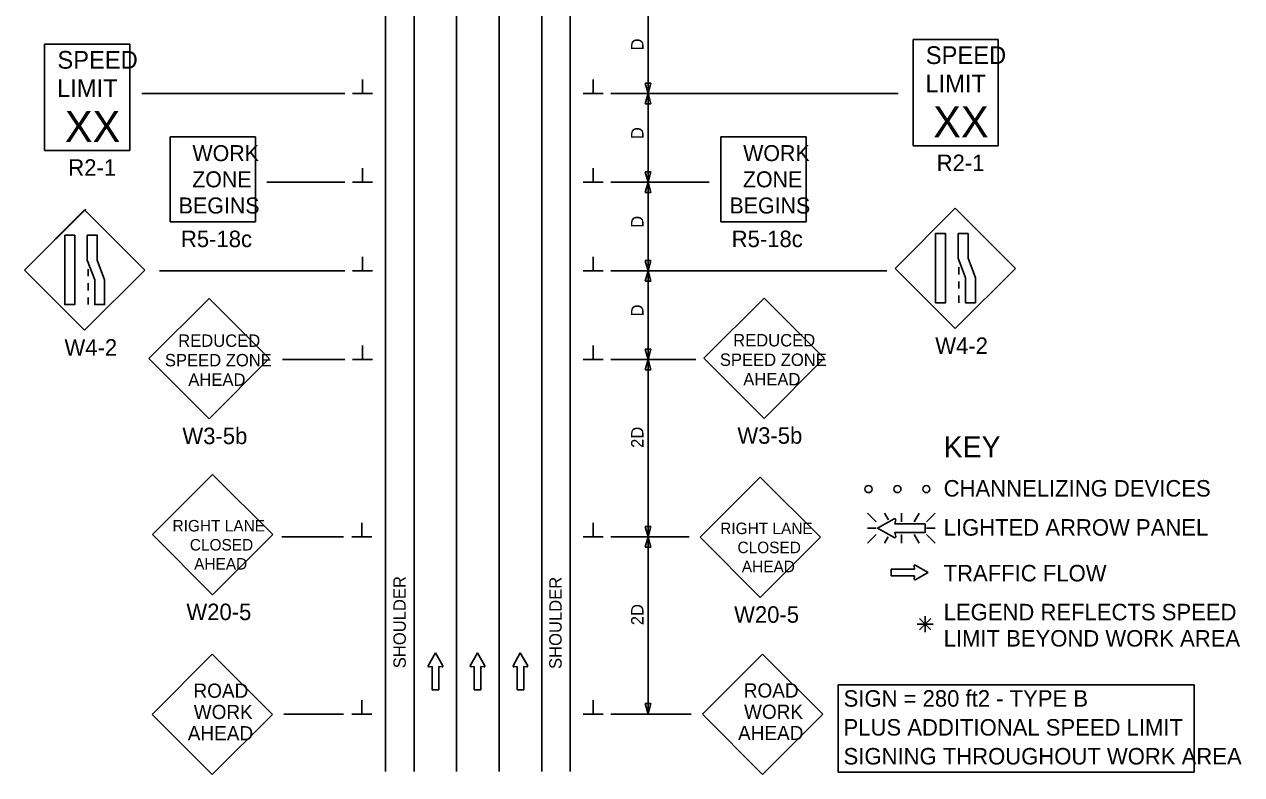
# Model space of a CAD drawing. Extents: x 16730 to 18475, y 5690 to 6927.
# Drawn here: x 16747 to 17434, y 6106 to 6529 of the extents above; entities that cross this region are included whole.
import ezdxf

# ---------------------------------------------------------------- set-up
doc = ezdxf.new("R2010")
doc.units = 0
for name, color, linetype in [('ALI_LEGAL_EX', 7, 'Continuous'), ('MT_SCRATCH_LEVEL_E', 7, 'Continuous'), ('PAVT_EDGE_EX', 7, 'Continuous'), ('TRAFFIC_SIGNS_PR', 7, 'Continuous'), ('TYPICAL_TEXT_DIMEN_EX', 7, 'Continuous'), ('TYPICAL_TEXT_DIMEN_PR', 7, 'Continuous')]:
    doc.layers.add(name, color=color, linetype=linetype)

msp = doc.modelspace()

# ---------------------------------------------------------------- linework, layer by layer
at = {"layer": 'ALI_LEGAL_EX'}
for p, q in [((16991.15, 6924.81), (16991.15, 6107.83)), ((17015.15, 6924.81), (17015.15, 6107.83))]:
    msp.add_line(p, q, dxfattribs=at)
for points in [[(16991.15, 6524.81), (16991.15, 6499.81)], [(17015.15, 6524.81), (17015.15, 6499.81)], [(16991.15, 6474.81), (16991.15, 6449.81)], [(17015.15, 6474.81), (17015.15, 6449.81)], [(16991.15, 6424.81), (16991.15, 6399.81)], [(17015.15, 6424.81), (17015.15, 6399.81)], [(16991.15, 6324.81), (16991.15, 6299.81)], [(17015.15, 6324.81), (17015.15, 6299.81)], [(16991.15, 6224.81), (16991.15, 6199.81)], [(17015.15, 6224.81), (17015.15, 6199.81)], [(16991.15, 6124.81), (16991.15, 6107.83)], [(17015.15, 6124.81), (17015.15, 6107.83)]]:
    msp.add_lwpolyline(points, dxfattribs=at)
at = {"layer": 'MT_SCRATCH_LEVEL_E'}
for p, q in [((17249.52, 6222.01), (17236.26, 6222.01)), ((17236.26, 6222.01), (17236.26, 6218.27)), ((17249.21, 6223.79), (17249.52, 6222.01)), ((17257.13, 6220.16), (17249.89, 6224.27)), ((17236.26, 6218.27), (17249.52, 6218.27)), ((17249.52, 6218.27), (17249.21, 6216.49)), ((17249.89, 6216.01), (17257.13, 6220.16)), ((16979.3, 6174.71), (16975.19, 6167.47)), ((16983.44, 6167.47), (16979.3, 6174.71)), ((17003, 6174.71), (16998.89, 6167.47)), ((17007.15, 6167.47), (17003, 6174.71)), ((17027.11, 6174.71), (17023, 6167.47)), ((17031.26, 6167.47), (17027.11, 6174.71)), ((16975.67, 6166.78), (16977.45, 6167.1)), ((16977.45, 6167.1), (16977.45, 6153.84)), ((16981.19, 6153.84), (16981.19, 6167.1)), ((16981.19, 6167.1), (16982.97, 6166.78)), ((16999.37, 6166.78), (17001.15, 6167.1)), ((17001.15, 6167.1), (17001.15, 6153.84)), ((17004.89, 6153.84), (17004.89, 6167.1)), ((17004.89, 6167.1), (17006.67, 6166.78)), ((17023.48, 6166.78), (17025.26, 6167.1)), ((17025.26, 6167.1), (17025.26, 6153.84)), ((17029, 6153.84), (17029, 6167.1)), ((17029, 6167.1), (17030.78, 6166.78)), ((16977.45, 6153.84), (16981.19, 6153.84)), ((17001.15, 6153.84), (17004.89, 6153.84)), ((17025.26, 6153.84), (17029, 6153.84))]:
    msp.add_line(p, q, dxfattribs=at)
for centre, start, end in [((17249.66, 6223.86), 60.42484, 189.96381), ((17249.66, 6216.42), 170.03619, 299.77312), ((16975.59, 6167.24), 150.42484, 279.96381), ((16983.04, 6167.25), 260.03619, 29.77312), ((16999.3, 6167.24), 150.42484, 279.96381), ((17006.74, 6167.25), 260.03619, 29.77312), ((17023.41, 6167.24), 150.42484, 279.96381), ((17030.85, 6167.25), 260.03619, 29.77312)]:
    msp.add_arc(centre, 0.463, start, end, dxfattribs=at)
at = {"layer": 'PAVT_EDGE_EX'}
for p, q in [((16951.15, 6927.15), (16951.15, 6107.83)), ((16967.15, 6927.15), (16967.15, 6107.83)), ((17039.15, 6927.15), (17039.15, 6107.83)), ((17055.15, 6927.15), (17055.15, 6107.83))]:
    msp.add_line(p, q, dxfattribs=at)
at = {"layer": 'TRAFFIC_SIGNS_PR'}
for p, q in [((16758.8, 6518.11), (16806.8, 6518.11)), ((16758.8, 6458.11), (16758.8, 6518.11)), ((16806.8, 6458.11), (16806.8, 6518.11)), ((17248.6, 6520.74), (17296.6, 6520.74)), ((17248.6, 6460.74), (17248.6, 6520.74)), ((17296.6, 6460.74), (17296.6, 6520.74)), ((16829.68, 6417.85), (16829.68, 6465.85)), ((16829.68, 6465.85), (16877.68, 6465.85)), ((16877.68, 6417.85), (16877.68, 6465.85)), ((17140.3, 6417.85), (17140.3, 6465.85)), ((17140.3, 6465.85), (17188.3, 6465.85)), ((17188.3, 6417.85), (17188.3, 6465.85)), ((16758.8, 6458.11), (16806.8, 6458.11)), ((17248.6, 6460.74), (17296.6, 6460.74)), ((16781.3, 6424.52), (16747.36, 6390.58)), ((16782, 6425.03), (16748.05, 6391.09)), ((16815.24, 6390.58), (16781.3, 6424.52)), ((17272.45, 6425.51), (17238.51, 6391.57)), ((17306.39, 6391.57), (17272.45, 6425.51)), ((16829.68, 6417.85), (16877.68, 6417.85)), ((17140.3, 6417.85), (17188.3, 6417.85)), ((16747.36, 6390.58), (16781.3, 6356.64)), ((16781.3, 6356.64), (16815.24, 6390.58)), ((16783.35, 6391.19), (16783.35, 6387.19)), ((17238.51, 6391.57), (17272.45, 6357.63)), ((17272.45, 6357.63), (17306.39, 6391.57)), ((17274.5, 6392.19), (17274.5, 6388.19)), ((16783.35, 6383.19), (16783.35, 6379.19)), ((17274.5, 6384.19), (17274.5, 6380.19)), ((16783.35, 6375.19), (16783.35, 6371.19)), ((16851.56, 6374.63), (16817.62, 6340.69)), ((16885.5, 6340.69), (16851.56, 6374.63)), ((17164.59, 6374.86), (17130.65, 6340.92)), ((17198.53, 6340.92), (17164.59, 6374.86)), ((17274.5, 6376.19), (17274.5, 6372.19)), ((16817.62, 6340.69), (16851.56, 6306.75)), ((16851.56, 6306.75), (16885.5, 6340.69)), ((17130.65, 6340.92), (17164.59, 6306.98)), ((17164.59, 6306.98), (17198.53, 6340.92)), ((16853.55, 6275.39), (16819.61, 6241.44)), ((16887.5, 6241.44), (16853.55, 6275.39)), ((17162.47, 6273.91), (17128.53, 6239.97)), ((17196.41, 6239.97), (17162.47, 6273.91)), ((17222.94, 6253.54), (17227.87, 6248.61)), ((17234.7, 6249.72), (17232.5, 6253.55)), ((17242.02, 6248.61), (17242.02, 6253.55)), ((17249.26, 6248.61), (17252.11, 6253.55)), ((17256.17, 6248.61), (17261.11, 6253.55)), ((16819.61, 6241.44), (16853.55, 6207.5)), ((16853.55, 6207.5), (16887.5, 6241.44)), ((17227.87, 6245.06), (17222.94, 6245.06)), ((17222.94, 6236.57), (17227.87, 6241.5)), ((17242.02, 6241.5), (17242.02, 6236.57)), ((17252.15, 6236.57), (17249.3, 6241.5)), ((17256.17, 6245.06), (17261.11, 6245.06)), ((17256.17, 6241.5), (17261.11, 6236.56)), ((17128.53, 6239.97), (17162.47, 6206.03)), ((17162.47, 6206.03), (17196.41, 6239.97)), ((17232.45, 6236.57), (17234.56, 6240.23)), ((16853.35, 6173.94), (16819.4, 6140)), ((16887.29, 6140), (16853.35, 6173.94)), ((17163.72, 6174.07), (17129.78, 6140.13)), ((17197.66, 6140.13), (17163.72, 6174.07)), ((16819.4, 6140), (16853.35, 6106.06)), ((16853.35, 6106.06), (16887.29, 6140)), ((17129.78, 6140.13), (17163.72, 6106.18)), ((17163.72, 6106.18), (17197.66, 6140.13))]:
    msp.add_line(p, q, dxfattribs=at)
for points in [[(16770.18, 6410.25), (16770.18, 6371.19), (16775.8, 6371.19), (16775.8, 6410.25)], [(16782.85, 6410.25), (16782.85, 6396.27), (16787.03, 6385.17), (16787.03, 6371.19), (16792.65, 6371.19), (16792.65, 6385.17), (16788.47, 6396.27), (16788.47, 6410.25)], [(17261.33, 6411.24), (17261.33, 6372.19), (17266.95, 6372.19), (17266.95, 6411.24)], [(17274, 6411.24), (17274, 6397.27), (17278.18, 6386.16), (17278.18, 6372.19), (17283.8, 6372.19), (17283.8, 6386.16), (17279.62, 6397.27), (17279.62, 6411.24)]]:
    msp.add_lwpolyline(points, close=True, dxfattribs=at)
for points in [[(17237.95, 6250.33), (17228.66, 6245.06), (17237.95, 6239.73)], [(17238.83, 6240.36), (17238.42, 6242.63), (17255.44, 6242.63), (17255.44, 6247.43), (17238.42, 6247.43), (17238.83, 6249.71)]]:
    msp.add_lwpolyline(points, dxfattribs=at)
for centre in [(17223.5, 6267.09), (17239.8, 6267.09), (17256.1, 6267.09)]:
    msp.add_circle(centre, 2, dxfattribs=at)
for centre, radius, start, end in [((17238.24, 6249.81), 0.598, 350.73078, 118.89165), ((17238.24, 6240.26), 0.597, 241.48329, 9.95933)]:
    msp.add_arc(centre, radius, start, end, dxfattribs=at)
at = {"layer": 'TYPICAL_TEXT_DIMEN_EX'}
msp.add_lwpolyline([(17206.43, 6156.8), (17407.1, 6156.8), (17407.1, 6107.48), (17206.43, 6107.48)], close=True, dxfattribs=at)
at = {"layer": 'TYPICAL_TEXT_DIMEN_PR'}
for p, q in [((17099.15, 6540.24), (17099.15, 6490.24)), ((16938.03, 6490.24), (16938.03, 6498.02)), ((17068.28, 6490.24), (17068.28, 6498.02)), ((17099.15, 6490.24), (17097.58, 6496.1)), ((17097.58, 6496.1), (17099.15, 6496.1)), ((17099.15, 6496.1), (17100.72, 6496.1)), ((17100.72, 6496.1), (17099.15, 6490.24)), ((16813.56, 6490.24), (16928.15, 6490.24)), ((16932.4, 6490.24), (16943.65, 6490.24)), ((17073.9, 6490.24), (17062.65, 6490.24)), ((17240.31, 6490.24), (17078.15, 6490.24)), ((17097.58, 6484.38), (17099.15, 6490.24)), ((17099.15, 6490.24), (17099.15, 6440.24)), ((17099.15, 6490.24), (17100.72, 6484.38)), ((17099.15, 6484.38), (17097.58, 6484.38)), ((17100.72, 6484.38), (17099.15, 6484.38)), ((16938.03, 6440.24), (16938.03, 6448.02)), ((17068.28, 6440.24), (17068.28, 6448.02)), ((17099.15, 6440.24), (17097.58, 6446.1)), ((17097.58, 6446.1), (17099.15, 6446.1)), ((17099.15, 6446.1), (17100.72, 6446.1)), ((17100.72, 6446.1), (17099.15, 6440.24)), ((16884.19, 6440.24), (16928.15, 6440.24)), ((16932.4, 6440.24), (16943.65, 6440.24)), ((17073.9, 6440.24), (17062.65, 6440.24)), ((17133.63, 6440.24), (17078.15, 6440.24)), ((17097.58, 6434.38), (17099.15, 6440.24)), ((17099.15, 6434.38), (17097.58, 6434.38)), ((17099.15, 6440.24), (17099.15, 6390.24)), ((17099.15, 6440.24), (17100.72, 6434.38)), ((17100.72, 6434.38), (17099.15, 6434.38)), ((16938.03, 6390.24), (16938.03, 6398.02)), ((17068.28, 6390.24), (17068.28, 6398.02)), ((17099.15, 6390.24), (17097.58, 6396.1)), ((17097.58, 6396.1), (17099.15, 6396.1)), ((17099.15, 6396.1), (17100.72, 6396.1)), ((17100.72, 6396.1), (17099.15, 6390.24)), ((16823.56, 6390.24), (16928.15, 6390.24)), ((16932.4, 6390.24), (16943.65, 6390.24)), ((17073.9, 6390.24), (17062.65, 6390.24)), ((17233.8, 6390.24), (17078.15, 6390.24)), ((17097.58, 6384.38), (17099.15, 6390.24)), ((17099.15, 6390.24), (17099.15, 6340.24)), ((17099.15, 6390.24), (17100.72, 6384.38)), ((17099.15, 6384.38), (17097.58, 6384.38)), ((17100.72, 6384.38), (17099.15, 6384.38)), ((16938.03, 6340.24), (16938.03, 6348.02)), ((17068.28, 6340.24), (17068.28, 6348.02)), ((17099.15, 6340.24), (17097.58, 6346.1)), ((17097.58, 6346.1), (17099.15, 6346.1)), ((17099.15, 6346.1), (17100.72, 6346.1)), ((17100.72, 6346.1), (17099.15, 6340.24)), ((16892.99, 6340.24), (16928.15, 6340.24)), ((16932.4, 6340.24), (16943.65, 6340.24)), ((17073.9, 6340.24), (17062.65, 6340.24)), ((17126.13, 6340.24), (17078.15, 6340.24)), ((17097.58, 6334.38), (17099.15, 6340.24)), ((17099.15, 6340.24), (17099.15, 6240.24)), ((17099.15, 6340.24), (17100.72, 6334.38)), ((17099.15, 6334.38), (17097.58, 6334.38)), ((17100.72, 6334.38), (17099.15, 6334.38)), ((16937.74, 6240.24), (16937.74, 6248.02)), ((17068.28, 6240.24), (17068.28, 6248.02)), ((17099.15, 6240.24), (17097.58, 6246.1)), ((17097.58, 6246.1), (17099.15, 6246.1)), ((17099.15, 6246.1), (17100.72, 6246.1)), ((17100.72, 6246.1), (17099.15, 6240.24)), ((16927.29, 6240.24), (16892.61, 6240.24)), ((16943.36, 6240.24), (16932.11, 6240.24)), ((17073.9, 6240.24), (17062.65, 6240.24)), ((17122.42, 6240.24), (17078.15, 6240.24)), ((17097.58, 6234.38), (17099.15, 6240.24)), ((17099.15, 6240.24), (17099.15, 6140.24)), ((17099.15, 6240.24), (17100.72, 6234.38)), ((17099.15, 6234.38), (17097.58, 6234.38)), ((17100.72, 6234.38), (17099.15, 6234.38)), ((17252.28, 6194.1), (17258.65, 6187.73)), ((17258.65, 6194.1), (17252.28, 6187.73)), ((17255.46, 6190.91), (17255.46, 6195.37)), ((17255.46, 6190.91), (17250.93, 6190.91)), ((17255.46, 6190.91), (17258.65, 6190.91)), ((17255.46, 6190.91), (17259.94, 6190.91)), ((17255.46, 6190.91), (17255.46, 6186.41)), ((16937.74, 6140.24), (16937.74, 6148.02)), ((17068.28, 6140.24), (17068.28, 6148.02)), ((17099.15, 6140.24), (17097.58, 6146.1)), ((17097.58, 6146.1), (17099.15, 6146.1)), ((17099.15, 6146.1), (17100.72, 6146.1)), ((17100.72, 6146.1), (17099.15, 6140.24)), ((16927.29, 6140.24), (16893.73, 6140.24)), ((16943.36, 6140.24), (16932.11, 6140.24)), ((17073.9, 6140.24), (17062.65, 6140.24)), ((17123.54, 6140.24), (17078.15, 6140.24))]:
    msp.add_line(p, q, dxfattribs=at)

# ---------------------------------------------------------------- texts
at = {"layer": 'TRAFFIC_SIGNS_PR'}
for s, height, p in [('SPEED', 10, (17255.81, 6506.82)), ('SPEED', 10, (16766.01, 6504.19)), ('LIMIT', 10, (16765.81, 6488.19)), ('LIMIT', 10, (17255.6, 6490.82)), ('XX', 17.538, (17259.99, 6465.44)), ('XX', 17.538, (16770.19, 6462.81)), ('WORK', 9.021, (16842.18, 6452.06)), ('WORK', 9.021, (17152.8, 6452.06)), ('R2-1', 9.3, (17261.94, 6446.44)), ('R2-1', 9.3, (16772.15, 6443.81)), ('ZONE', 9.021, (16842.03, 6437.29)), ('ZONE', 9.021, (17152.65, 6437.29)), ('BEGINS', 9.021, (16834.44, 6422.53)), ('BEGINS', 9.021, (17145.06, 6422.53)), ('R5-18c', 9.3, (16835.69, 6403.55)), ('R5-18c', 9.3, (17146.32, 6403.55)), ('W4-2', 9.3, (16770, 6342.34)), ('REDUCED', 7, (16834.13, 6347.32)), ('REDUCED', 7, (17147.16, 6347.56)), ('W4-2', 9.3, (17261.15, 6343.33)), ('SPEED ZONE', 7, (16826.63, 6336.32)), ('SPEED ZONE', 7, (17139.65, 6336.56)), ('AHEAD', 7, (16839.83, 6325.32)), ('AHEAD', 7, (17152.85, 6325.56)), ('W3-5b', 9.3, (16836.5, 6292.45)), ('W3-5b', 9.3, (17149.53, 6292.68)), ('RIGHT LANE', 6.5, (16830.96, 6243.19)), ('RIGHT LANE', 6.5, (17139.87, 6241.71)), ('CLOSED', 6.5, (16840.7, 6232.44)), ('CLOSED', 6.5, (17149.61, 6230.96)), ('AHEAD', 6.5, (16843.13, 6221.69)), ('AHEAD', 6.5, (17152.05, 6220.21)), ('W20-5', 9.3, (16838.77, 6193.21)), ('W20-5', 9.3, (17147.69, 6191.73)), ('ROAD', 8, (16842.77, 6149.42)), ('ROAD', 8, (17153.15, 6149.54)), ('WORK', 8, (16842.91, 6137.42)), ('WORK', 8, (17153.28, 6137.54)), ('AHEAD', 8, (16839.55, 6125.42)), ('AHEAD', 8, (17149.92, 6125.54))]:
    msp.add_text(s, height=height, dxfattribs=at).set_placement(p)
at = {"layer": 'TYPICAL_TEXT_DIMEN_EX'}
for s, height, p in [('KEY', 12, (17265.88, 6284.95)), ('CHANNELIZING DEVICES', 9.3, (17265.88, 6262.9)), ('LIGHTED ARROW PANEL', 9.3, (17265.88, 6240.85)), ('TRAFFIC FLOW', 9.3, (17265.88, 6215.05)), ('LEGEND REFLECTS SPEED', 9.3, (17265.88, 6193.1)), ('LIMIT BEYOND WORK AREA', 9.3, (17265.88, 6178.3)), ('SIGN = 280 ft2 - TYPE B', 9.3, (17209.44, 6144.4)), ('PLUS ADDITIONAL SPEED LIMIT', 9.3, (17209.44, 6128.1)), ('SIGNING THROUGHOUT WORK AREA', 9.3, (17209.44, 6111.8))]:
    msp.add_text(s, height=height, dxfattribs=at).set_placement(p)
at = {"layer": 'TYPICAL_TEXT_DIMEN_PR'}
for s, p in [('D', (17096.59, 6514.46)), ('D', (17096.59, 6464.46)), ('D', (17096.59, 6414.46)), ('D', (17096.59, 6364.46)), ('2D', (17096.59, 6290.32)), ('SHOULDER', (16962.51, 6166.05)), ('SHOULDER', (17050.43, 6165.64)), ('2D', (17096.59, 6190.32))]:
    msp.add_text(s, height=7, rotation=90, dxfattribs=at).set_placement(p)

doc.saveas('drawing.dxf')
